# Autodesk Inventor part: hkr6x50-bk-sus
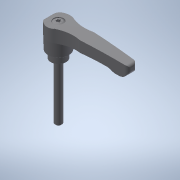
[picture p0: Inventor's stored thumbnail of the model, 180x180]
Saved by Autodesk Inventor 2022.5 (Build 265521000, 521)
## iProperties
Created: 2017-09
Part Number: hkr6x50-bk-sus
Material: 一般
Document SubType Name: Modeling
Designer: imaocorp
Density: 1 g/cm^3
Appearance: 既定
Author: imaocorp
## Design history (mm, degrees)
node "hkr6x50-bk-sus.x_t1"
node "hkr6x50-bk-sus"
node "Base1"
